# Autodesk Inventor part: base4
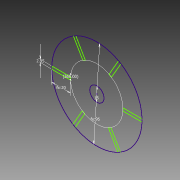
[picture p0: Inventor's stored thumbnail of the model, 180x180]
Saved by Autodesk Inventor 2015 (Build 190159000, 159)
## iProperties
Created: 2017-04
Part Number: base4
Material: Generic
Document SubType Name: Modeling
Designer: mcalderon
Density: 1 g/cm^3
Appearance: Default
Author: mcalderon
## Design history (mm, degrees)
sketch "Sketch1"
  geometry: L1 (27.536, 1.807)-(47.466, 1.807); L2 (47.486, -1.143)-(27.486, -1.143); L3 (27.486, -1.143)-(27.536, 1.807); L4 (12.204, 24.751)-(22.168, 42.01); L5 (24.733, 40.553)-(14.733, 23.232); L6 (14.733, 23.232)-(12.204, 24.751); L7 (-15.333, 22.944)-(-25.298, 40.203); L8 (-22.753, 41.696)-(-12.753, 24.375); L9 (-12.753, 24.375)-(-15.333, 22.944); L10 (-27.536, -1.807)-(-47.466, -1.807); L11 (-47.486, 1.143)-(-27.486, 1.143); L12 (-27.486, 1.143)-(-27.536, -1.807); L13 (-12.204, -24.751)-(-22.168, -42.01); L14 (-24.733, -40.553)-(-14.733, -23.232); L15 (-14.733, -23.232)-(-12.204, -24.751); L16 (15.333, -22.944)-(25.298, -40.203); L17 (22.753, -41.696)-(12.753, -24.375); L18 (12.753, -24.375)-(15.333, -22.944); C1 r 7.5 at (0, 0); A1 r 47.5 centre (0, 0) between (47.5, 0) and (47.466, 1.807); 1 further point
  constraints: 36 end point, 3 point on circle, 2 centre point, 2 coincident, 1 horizontal, 1 parallel, 43 other
  dimensions: "d0" = 15 diameter of C1; "d1" = 95 diameter of A1 (= d0 + 2 x space); "d2" = 20 distance of L2.start L2.end (= 0.5 x space); "d3" = 2.95 distance of L1.end L2.start; "d6" = 360 deg dimension on point (0, 0) L1.start (derived)
